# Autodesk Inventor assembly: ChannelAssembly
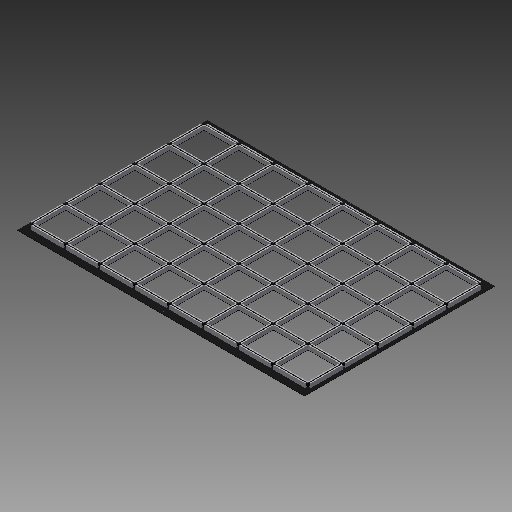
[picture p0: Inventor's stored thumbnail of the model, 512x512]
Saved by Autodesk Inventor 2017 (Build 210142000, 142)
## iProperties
Created: 2017-05
Part Number: ChannelAssembly
Document SubType Name: Assembly
Designer: Savy
Author: Savy
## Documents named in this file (4)
- D:\3D Printer Designs\John Ledden Designs\Infinity Mirror Table\SavanDrawings\ChannelAssembly.iam
- D:\3D Printer Designs\John Ledden Designs\Infinity Mirror Table\SavanDrawings\UChannel.ipt
- D:\3D Printer Designs\John Ledden Designs\Infinity Mirror Table\SavanDrawings\LEDStrip.ipt
- D:\3D Printer Designs\John Ledden Designs\Infinity Mirror Table\SavanDrawings\TopCutout_Cover.ipt
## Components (103 placed, 102 different names)
1. UChannel_1023
2. UChannel_1024
3. UChannel_1026
4. UChannel_1027
5. UChannel_1029
6. UChannel_1030
7. UChannel_1032
8. UChannel_1033
9. UChannel_1035 — Mate:2
10. UChannel_1036
11. UChannel_1038
12. UChannel_1039
13. UChannel_1041
14. UChannel_1042
15. UChannel_1044
16. UChannel_1045
17. UChannel_1047
18. UChannel_1048
19. UChannel_1050
20. UChannel_1051
21. UChannel_1053
22. UChannel_1054
23. UChannel_1056
24. UChannel_1057
25. UChannel_1059
26. UChannel_1060
27. UChannel_1062
28. UChannel_1063
29. UChannel_1065
30. UChannel_1066
31. UChannel_1068
32. UChannel_1069
33. UChannel_1071
34. UChannel_1072
35. UChannel_1074
36. UChannel_1075
37. UChannel_1077
38. UChannel_1078
39. UChannel_1080
40. UChannel_1081
41. UChannel_1083
42. UChannel_1084
43. UChannel_1086
44. UChannel_1087
45. UChannel_1089
46. UChannel_1090
47. UChannel_1092
48. UChannel_1093
49. UChannel_1095
50. UChannel_1096
51. UChannel_1098
52. UChannel_1099
53. UChannel_1101
54. UChannel_1102
55. UChannel_1104
56. UChannel_1105
57. UChannel_1107
58. UChannel_1108
59. UChannel_1110
60. UChannel_1111
61. UChannel_1113
62. UChannel_1114
63. UChannel_1116
64. UChannel_1117
65. UChannel_1119
66. UChannel_1120
67. UChannel_1122
68. UChannel_1123
69. UChannel_1125
70. UChannel_1126
71. UChannel_1128
72. UChannel_1129 — Flush:2
73. UChannel_1131
74. UChannel_1132
75. UChannel_1134
76. UChannel_1135
77. UChannel_1137
78. UChannel_1138
79. UChannel_1140
80. UChannel_1141
81. UChannel_1143
82. UChannel_1145
83. UChannel_1147
84. UChannel_1149 — Mate:1
85. UChannel_1151
86. UChannel_1153
87. UChannel_1155
88. UChannel_1157
89. UChannel_1159
90. UChannel_1161
91. UChannel_1163
92. UChannel_1165
93. UChannel_1167 — Flush:1
94. LEDStrip_1169
95. LEDStrip_1170
96. LEDStrip_1171
97. LEDStrip_1172
98. LEDStrip_1173
99. LEDStrip_1174
100. LEDStrip_1175
101. LEDStrip_1176
102. TopCutout_Cover:1 — Mate:1, Flush:1, Flush:2, Mate:3, Flush:3
103. TopCutout_Cover:2 — Mate:2, Mate:3, Flush:3
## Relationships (6: Mate 3, Flush 3)
- Mate:1: UChannel_1149 ↔ TopCutout_Cover:1
- Flush:1: UChannel_1167 ↔ TopCutout_Cover:1
- Flush:2: UChannel_1129 ↔ TopCutout_Cover:1
- Mate:2: UChannel_1035 ↔ TopCutout_Cover:2
- Mate:3: TopCutout_Cover:1 ↔ TopCutout_Cover:2
- Flush:3: TopCutout_Cover:1 ↔ TopCutout_Cover:2
